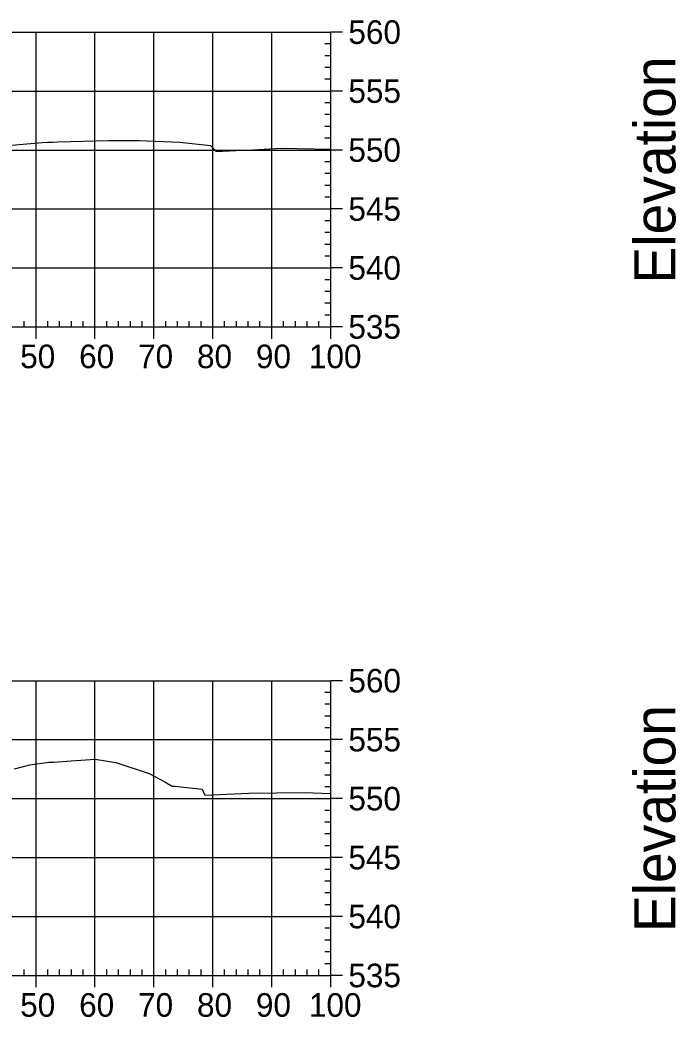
# Model space of a CAD drawing. Extents: x 708103 to 717568, y 374476 to 378707.
# Drawn here: x 710474.2 to 710585.6, y 377647.6 to 377816.7 of the extents above; entities that cross this region are included whole.
import ezdxf

# ---------------------------------------------------------------- set-up
doc = ezdxf.new("R2010")
doc.units = 0
for name, color, linetype in [('57', 7, 'Continuous'), ('60', 7, 'Continuous'), ('Existing', 7, 'Continuous')]:
    doc.layers.add(name, color=color, linetype=linetype)

msp = doc.modelspace()

# ---------------------------------------------------------------- linework, layer by layer
at = {"layer": '57'}
for p, q in [((710326.98, 377814.63), (710526.98, 377814.63)), ((710476.98, 377764.63), (710476.98, 377814.63)), ((710486.98, 377764.63), (710486.98, 377814.63)), ((710496.98, 377764.63), (710496.98, 377814.63)), ((710506.98, 377764.63), (710506.98, 377814.63)), ((710516.98, 377764.63), (710516.98, 377814.63)), ((710526.98, 377764.63), (710526.98, 377814.63)), ((710526.98, 377764.63), (710526.98, 377814.63)), ((710528.98, 377814.63), (710526.98, 377814.63)), ((710526.98, 377812.63), (710525.98, 377812.63)), ((710526.98, 377810.63), (710525.98, 377810.63)), ((710526.98, 377808.63), (710525.98, 377808.63)), ((710526.98, 377806.63), (710525.98, 377806.63)), ((710326.98, 377804.63), (710526.98, 377804.63)), ((710528.98, 377804.63), (710526.98, 377804.63)), ((710526.98, 377802.63), (710525.98, 377802.63)), ((710526.98, 377800.63), (710525.98, 377800.63)), ((710526.98, 377798.63), (710525.98, 377798.63)), ((710526.98, 377796.63), (710525.98, 377796.63)), ((710326.98, 377794.63), (710526.98, 377794.63)), ((710528.98, 377794.63), (710526.98, 377794.63)), ((710526.98, 377792.63), (710525.98, 377792.63)), ((710526.98, 377790.63), (710525.98, 377790.63)), ((710526.98, 377788.63), (710525.98, 377788.63)), ((710526.98, 377786.63), (710525.98, 377786.63)), ((710326.98, 377784.63), (710526.98, 377784.63)), ((710528.98, 377784.63), (710526.98, 377784.63)), ((710526.98, 377782.63), (710525.98, 377782.63)), ((710526.98, 377780.63), (710525.98, 377780.63)), ((710526.98, 377778.63), (710525.98, 377778.63)), ((710526.98, 377776.63), (710525.98, 377776.63)), ((710326.98, 377774.63), (710526.98, 377774.63)), ((710528.98, 377774.63), (710526.98, 377774.63)), ((710526.98, 377772.63), (710525.98, 377772.63)), ((710526.98, 377770.63), (710525.98, 377770.63)), ((710526.98, 377768.63), (710525.98, 377768.63)), ((710474.98, 377764.63), (710474.98, 377765.63)), ((710478.98, 377764.63), (710478.98, 377765.63)), ((710480.98, 377764.63), (710480.98, 377765.63)), ((710482.98, 377764.63), (710482.98, 377765.63)), ((710484.98, 377764.63), (710484.98, 377765.63)), ((710488.98, 377764.63), (710488.98, 377765.63)), ((710490.98, 377764.63), (710490.98, 377765.63)), ((710492.98, 377764.63), (710492.98, 377765.63)), ((710494.98, 377764.63), (710494.98, 377765.63)), ((710498.98, 377764.63), (710498.98, 377765.63)), ((710500.98, 377764.63), (710500.98, 377765.63)), ((710502.98, 377764.63), (710502.98, 377765.63)), ((710504.98, 377764.63), (710504.98, 377765.63)), ((710508.98, 377764.63), (710508.98, 377765.63)), ((710510.98, 377764.63), (710510.98, 377765.63)), ((710512.98, 377764.63), (710512.98, 377765.63)), ((710514.98, 377764.63), (710514.98, 377765.63)), ((710518.98, 377764.63), (710518.98, 377765.63)), ((710520.98, 377764.63), (710520.98, 377765.63)), ((710522.98, 377764.63), (710522.98, 377765.63)), ((710524.98, 377764.63), (710524.98, 377765.63)), ((710526.98, 377766.63), (710525.98, 377766.63)), ((710326.98, 377764.63), (710526.98, 377764.63)), ((710326.98, 377764.63), (710526.98, 377764.63)), ((710476.98, 377762.63), (710476.98, 377764.63)), ((710486.98, 377762.63), (710486.98, 377764.63)), ((710496.98, 377762.63), (710496.98, 377764.63)), ((710506.98, 377762.63), (710506.98, 377764.63)), ((710516.98, 377762.63), (710516.98, 377764.63)), ((710526.98, 377762.63), (710526.98, 377764.63)), ((710528.98, 377764.63), (710526.98, 377764.63)), ((710326.98, 377704.63), (710526.98, 377704.63)), ((710476.98, 377654.63), (710476.98, 377704.63)), ((710486.98, 377654.63), (710486.98, 377704.63)), ((710496.98, 377654.63), (710496.98, 377704.63)), ((710506.98, 377654.63), (710506.98, 377704.63)), ((710516.98, 377654.63), (710516.98, 377704.63)), ((710526.98, 377654.63), (710526.98, 377704.63)), ((710526.98, 377654.63), (710526.98, 377704.63)), ((710528.98, 377704.63), (710526.98, 377704.63)), ((710526.98, 377702.63), (710525.98, 377702.63)), ((710526.98, 377700.63), (710525.98, 377700.63)), ((710526.98, 377698.63), (710525.98, 377698.63)), ((710526.98, 377696.63), (710525.98, 377696.63)), ((710326.98, 377694.63), (710526.98, 377694.63)), ((710528.98, 377694.63), (710526.98, 377694.63)), ((710526.98, 377692.63), (710525.98, 377692.63)), ((710526.98, 377690.63), (710525.98, 377690.63)), ((710526.98, 377688.63), (710525.98, 377688.63)), ((710526.98, 377686.63), (710525.98, 377686.63)), ((710326.98, 377684.63), (710526.98, 377684.63)), ((710528.98, 377684.63), (710526.98, 377684.63)), ((710526.98, 377682.63), (710525.98, 377682.63)), ((710526.98, 377680.63), (710525.98, 377680.63)), ((710526.98, 377678.63), (710525.98, 377678.63)), ((710526.98, 377676.63), (710525.98, 377676.63)), ((710326.98, 377674.63), (710526.98, 377674.63)), ((710528.98, 377674.63), (710526.98, 377674.63)), ((710526.98, 377672.63), (710525.98, 377672.63)), ((710526.98, 377670.63), (710525.98, 377670.63)), ((710526.98, 377668.63), (710525.98, 377668.63)), ((710526.98, 377666.63), (710525.98, 377666.63)), ((710326.98, 377664.63), (710526.98, 377664.63)), ((710528.98, 377664.63), (710526.98, 377664.63)), ((710526.98, 377662.63), (710525.98, 377662.63)), ((710526.98, 377660.63), (710525.98, 377660.63)), ((710526.98, 377658.63), (710525.98, 377658.63)), ((710474.98, 377654.63), (710474.98, 377655.63)), ((710478.98, 377654.63), (710478.98, 377655.63)), ((710480.98, 377654.63), (710480.98, 377655.63)), ((710482.98, 377654.63), (710482.98, 377655.63)), ((710484.98, 377654.63), (710484.98, 377655.63)), ((710488.98, 377654.63), (710488.98, 377655.63)), ((710490.98, 377654.63), (710490.98, 377655.63)), ((710492.98, 377654.63), (710492.98, 377655.63)), ((710494.98, 377654.63), (710494.98, 377655.63)), ((710498.98, 377654.63), (710498.98, 377655.63)), ((710500.98, 377654.63), (710500.98, 377655.63)), ((710502.98, 377654.63), (710502.98, 377655.63)), ((710504.98, 377654.63), (710504.98, 377655.63)), ((710508.98, 377654.63), (710508.98, 377655.63)), ((710510.98, 377654.63), (710510.98, 377655.63)), ((710512.98, 377654.63), (710512.98, 377655.63)), ((710514.98, 377654.63), (710514.98, 377655.63)), ((710518.98, 377654.63), (710518.98, 377655.63)), ((710520.98, 377654.63), (710520.98, 377655.63)), ((710522.98, 377654.63), (710522.98, 377655.63)), ((710524.98, 377654.63), (710524.98, 377655.63)), ((710526.98, 377656.63), (710525.98, 377656.63)), ((710326.98, 377654.63), (710526.98, 377654.63)), ((710326.98, 377654.63), (710526.98, 377654.63)), ((710476.98, 377652.63), (710476.98, 377654.63)), ((710486.98, 377652.63), (710486.98, 377654.63)), ((710496.98, 377652.63), (710496.98, 377654.63)), ((710506.98, 377652.63), (710506.98, 377654.63)), ((710516.98, 377652.63), (710516.98, 377654.63)), ((710526.98, 377652.63), (710526.98, 377654.63)), ((710528.98, 377654.63), (710526.98, 377654.63))]:
    msp.add_line(p, q, dxfattribs=at)
at = {"layer": 'Existing'}
for points in [[(710468.89, 377795.09), (710478.02, 377795.9), (710478.93, 377795.94), (710479.84, 377795.97), (710480.7, 377796), (710489.34, 377796.25), (710490.29, 377796.26), (710491.2, 377796.26), (710492.04, 377796.24), (710493.63, 377796.26), (710494.44, 377796.22), (710501.39, 377795.98), (710506.6, 377795.38), (710507.47, 377794.42), (710507.51, 377794.36), (710512.11, 377794.59), (710513.83, 377794.67), (710518.48, 377794.94), (710526.98, 377794.76)], [(710473.32, 377689.65), (710475.9, 377690.37), (710479.17, 377690.82), (710480.04, 377690.8), (710482.94, 377691.04), (710486.99, 377691.33), (710490.5, 377690.73), (710496.16, 377688.87), (710498.86, 377687.45), (710500.08, 377686.74), (710500.55, 377686.71), (710505.18, 377686.22), (710505.34, 377685.85), (710505.62, 377685.2), (710513.06, 377685.56), (710522.45, 377685.64), (710526.98, 377685.52)]]:
    msp.add_lwpolyline(points, dxfattribs=at)

# ---------------------------------------------------------------- texts
at = {"layer": '57'}
for s, p in [('560', (710529.98, 377812.63)), ('555', (710529.98, 377802.63)), ('550', (710529.98, 377792.63)), ('545', (710529.98, 377782.63)), ('540', (710529.98, 377772.63)), ('535', (710529.98, 377762.63)), ('50', (710474.29, 377757.63)), ('60', (710484.29, 377757.63)), ('70', (710494.29, 377757.63)), ('80', (710504.29, 377757.63)), ('90', (710514.29, 377757.63)), ('100', (710523.28, 377757.63)), ('560', (710529.98, 377702.63)), ('555', (710529.98, 377692.63)), ('550', (710529.98, 377682.63)), ('545', (710529.98, 377672.63)), ('540', (710529.98, 377662.63)), ('535', (710529.98, 377652.63)), ('50', (710474.29, 377647.63)), ('60', (710484.29, 377647.63)), ('70', (710494.29, 377647.63)), ('80', (710504.29, 377647.63)), ('90', (710514.29, 377647.63)), ('100', (710523.28, 377647.63))]:
    msp.add_text(s, height=4, dxfattribs=at).set_placement(p)
at = {"layer": '60'}
for p in [(710585.48, 377771.99), (710585.48, 377661.99)]:
    msp.add_text('Elevation', height=7, rotation=90, dxfattribs=at).set_placement(p)

doc.saveas('drawing.dxf')
